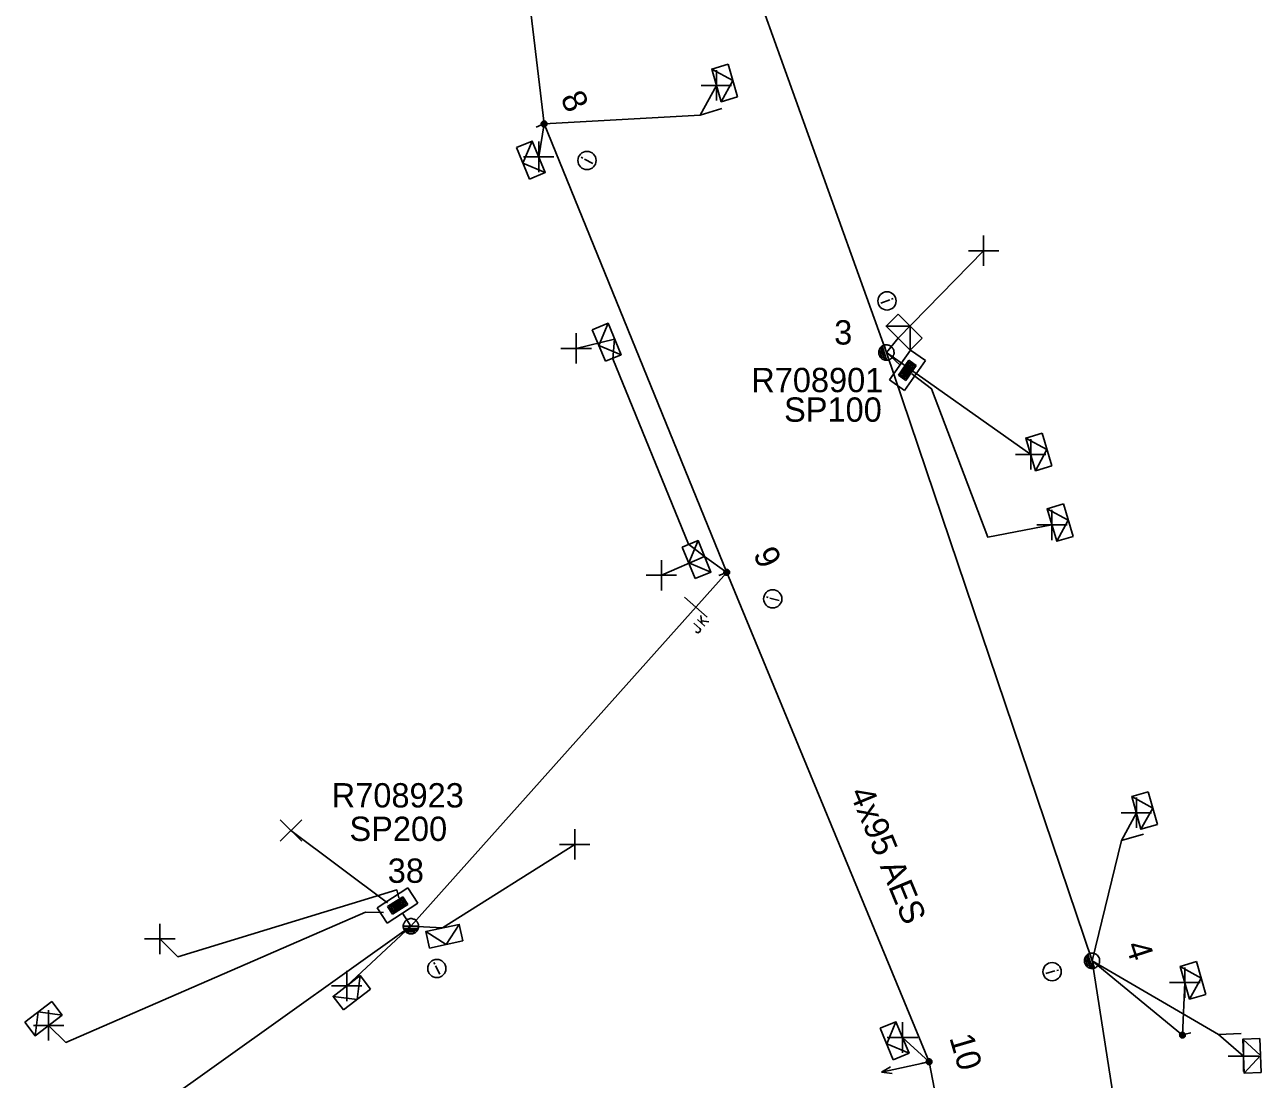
# Model space of a CAD drawing. Extents: x -540466 to -537383, y -1184038 to -1179972.
# Drawn here: x -537738 to -537687.2, y -1180420.7 to -1180377.4 of the extents above; entities that cross this region are included whole.
import ezdxf

# ---------------------------------------------------------------- set-up
doc = ezdxf.new("R2010")
doc.units = 0
for name, color, linetype in [('Vrstva 1', 7, 'Continuous'), ('Vrstva 10', 7, 'Continuous'), ('Vrstva 13', 7, 'Continuous'), ('Vrstva 14', 7, 'Continuous'), ('Vrstva 15', 7, 'Continuous'), ('Vrstva 18', 7, 'Continuous'), ('Vrstva 2', 7, 'Continuous'), ('Vrstva 28', 7, 'Continuous'), ('Vrstva 29', 7, 'Continuous'), ('Vrstva 30', 7, 'Continuous'), ('Vrstva 31', 7, 'Continuous'), ('Vrstva 34', 7, 'Continuous'), ('Vrstva 36', 7, 'Continuous'), ('Vrstva 5', 7, 'Continuous'), ('Vrstva 50', 7, 'Continuous'), ('Vrstva 51', 7, 'Continuous'), ('Vrstva 52', 7, 'Continuous'), ('Vrstva 54', 7, 'Continuous'), ('Vrstva 59', 7, 'Continuous'), ('Vrstva 8', 7, 'Continuous'), ('Vrstva 9', 7, 'Continuous')]:
    doc.layers.add(name, color=color, linetype=linetype)

# ---------------------------------------------------------------- blocks, each defined once
blk = doc.blocks.new('NN440')
at = {"layer": 'Vrstva 2'}
for points in [[(0.63, 0), (0.63, 0.06), (0.62, 0.13), (0.6, 0.19), (0.58, 0.25), (0.55, 0.31), (0.51, 0.37), (0.47, 0.42), (0.42, 0.46), (0.37, 0.51), (0.32, 0.54), (0.26, 0.57), (0.2, 0.59), (0.13, 0.61), (0.07, 0.62), (0, 0.63), (-0.06, 0.62), (-0.13, 0.61), (-0.19, 0.59), (-0.26, 0.57), (-0.31, 0.54), (-0.37, 0.51), (-0.42, 0.46), (-0.47, 0.42), (-0.51, 0.37), (-0.54, 0.31), (-0.57, 0.25), (-0.6, 0.19), (-0.62, 0.13), (-0.63, 0.06), (-0.63, 0), (-0.63, -0.07), (-0.62, -0.14), (-0.6, -0.2), (-0.57, -0.26), (-0.54, -0.32), (-0.51, -0.37), (-0.47, -0.43), (-0.42, -0.47), (-0.37, -0.51), (-0.31, -0.55), (-0.26, -0.58), (-0.19, -0.6), (-0.13, -0.62), (-0.06, -0.63), (0, -0.63), (0.07, -0.63), (0.13, -0.62), (0.2, -0.6), (0.26, -0.58), (0.32, -0.55), (0.37, -0.51), (0.42, -0.47), (0.47, -0.43), (0.51, -0.37), (0.55, -0.32), (0.58, -0.26), (0.6, -0.2), (0.62, -0.14), (0.63, -0.07), (0.63, 0)], [(-0.63, 0), (0.63, 0)], [(-0.6, -0.18), (0.57, -0.18)], [(-0.51, -0.32), (0.5, -0.32)], [(-0.37, -0.47), (0.35, -0.47)]]:
    blk.add_lwpolyline(points, dxfattribs=at)
blk = doc.blocks.new('NN560')
at = {"layer": 'Vrstva 2'}
for points in [[(1.999, -0.001), (1.59, 0.141)], [(0, -0.001), (1.999, -0.001)], [(1.999, -0.001), (1.59, -0.134)]]:
    blk.add_lwpolyline(points, dxfattribs=at)
blk = doc.blocks.new('NN840')
at = {"layer": 'Vrstva 15'}
for points in [[(0.003, 0.619), (0.003, -0.631)], [(-0.538, -0.385), (-0.538, -0.71)], [(-0.332, -0.385), (-0.332, -0.798)], [(-0.332, -0.641), (-0.125, -0.385)], [(-0.745, -0.71), (-0.745, -0.66)], [(-0.73, -0.764), (-0.745, -0.71)], [(-0.657, -0.798), (-0.73, -0.764)], [(-0.627, -0.798), (-0.657, -0.798)], [(-0.558, -0.764), (-0.627, -0.798)], [(-0.538, -0.71), (-0.558, -0.764)], [(-0.263, -0.557), (-0.091, -0.798)]]:
    blk.add_lwpolyline(points, dxfattribs=at)
blk = doc.blocks.new('NN770')
at = {"layer": 'Vrstva 10'}
for p, q in [((0.002, 0.187), (0.002, 0.263)), ((0.002, -0.276), (0.002, 0.111))]:
    blk.add_line(p, q, dxfattribs=at)
blk.add_circle((0, -0.008), 0.375, dxfattribs=at)
blk = doc.blocks.new('NN800')
at = {"layer": 'Vrstva 1'}
for points in [[(-0.442, 0.442), (0.442, -0.442)], [(-0.442, -0.442), (0.442, 0.442)]]:
    blk.add_lwpolyline(points, dxfattribs=at)
blk = doc.blocks.new('NN620')
at = {"layer": 'Vrstva 8'}
for points in [[(0.752, 0.004), (-0.748, 0.004)], [(-0.748, 0.004), (-0.748, -0.746)], [(0.752, -0.746), (0.752, 0.004)], [(0.368, -0.18), (-0.376, -0.18)], [(-0.376, -0.18), (-0.376, -0.558)], [(0.321, -0.227), (-0.329, -0.227)], [(-0.329, -0.227), (-0.329, -0.51)], [(0.274, -0.274), (-0.281, -0.274)], [(-0.281, -0.274), (-0.281, -0.463)], [(-0.281, -0.463), (0.274, -0.463)], [(0.227, -0.321), (-0.234, -0.321)], [(-0.234, -0.321), (-0.234, -0.416)], [(-0.234, -0.416), (0.227, -0.416)], [(-0.193, -0.369), (0.185, -0.369)], [(0.227, -0.416), (0.227, -0.321)], [(0.274, -0.463), (0.274, -0.274)], [(0.321, -0.51), (0.321, -0.227)], [(0.368, -0.558), (0.368, -0.18)], [(-0.748, -0.746), (0.752, -0.746)], [(-0.376, -0.558), (0.368, -0.558)], [(-0.329, -0.51), (0.321, -0.51)]]:
    blk.add_lwpolyline(points, dxfattribs=at)
blk = doc.blocks.new('NN630')
at = {"layer": 'Vrstva 9'}
for points in [[(-0.003, -0.7), (-0.703, 0)], [(-0.703, -0.7), (-0.703, 0), (0.697, 0), (0.697, -0.7)], [(-0.003, -0.7), (0.697, 0)], [(-0.703, -0.7), (0.697, -0.7)]]:
    blk.add_lwpolyline(points, dxfattribs=at)
blk = doc.blocks.new('NN500')
at = {"layer": 'Vrstva 2'}
for points in [[(0, -0.24), (0.02, -0.23), (0.05, -0.23), (0.07, -0.22), (0.09, -0.22), (0.12, -0.2), (0.14, -0.19), (0.16, -0.18), (0.17, -0.16), (0.19, -0.14), (0.2, -0.12), (0.21, -0.1), (0.22, -0.07), (0.23, -0.05), (0.23, -0.02), (0.23, 0), (0.23, 0.02), (0.23, 0.05), (0.22, 0.07), (0.21, 0.1), (0.2, 0.12), (0.19, 0.14), (0.17, 0.16), (0.16, 0.17), (0.14, 0.19), (0.12, 0.2), (0.09, 0.21), (0.07, 0.22), (0.05, 0.23), (0.02, 0.23), (0, 0.23), (-0.03, 0.23), (-0.05, 0.23), (-0.07, 0.22), (-0.1, 0.21), (-0.12, 0.2), (-0.14, 0.19), (-0.16, 0.17), (-0.18, 0.16), (-0.19, 0.14), (-0.2, 0.12), (-0.22, 0.1), (-0.22, 0.07), (-0.23, 0.05), (-0.23, 0.02), (-0.24, 0), (-0.23, -0.02), (-0.23, -0.05), (-0.22, -0.07), (-0.22, -0.1), (-0.2, -0.12), (-0.19, -0.14), (-0.18, -0.16), (-0.16, -0.18), (-0.14, -0.19), (-0.12, -0.2), (-0.1, -0.22), (-0.07, -0.22), (-0.05, -0.23), (-0.03, -0.23), (0, -0.24)], [(0, -0.24), (0.02, -0.23), (0.05, -0.23), (0.07, -0.22), (0.09, -0.22), (0.12, -0.2), (0.14, -0.19), (0.16, -0.18), (0.17, -0.16), (0.19, -0.14), (0.2, -0.12), (0.21, -0.1), (0.22, -0.07), (0.23, -0.05), (0.23, -0.02), (0.23, 0), (0.23, 0.02), (0.23, 0.05), (0.22, 0.07), (0.21, 0.1), (0.2, 0.12), (0.19, 0.14), (0.17, 0.16), (0.16, 0.17), (0.14, 0.19), (0.12, 0.2), (0.09, 0.21), (0.07, 0.22), (0.05, 0.23), (0.02, 0.23), (0, 0.23), (-0.03, 0.23), (-0.05, 0.23), (-0.07, 0.22), (-0.1, 0.21), (-0.12, 0.2), (-0.14, 0.19), (-0.16, 0.17), (-0.18, 0.16), (-0.19, 0.14), (-0.2, 0.12), (-0.22, 0.1), (-0.22, 0.07), (-0.23, 0.05), (-0.23, 0.02), (-0.24, 0), (-0.23, -0.02), (-0.23, -0.05), (-0.22, -0.07), (-0.22, -0.1), (-0.2, -0.12), (-0.19, -0.14), (-0.18, -0.16), (-0.16, -0.18), (-0.14, -0.19), (-0.12, -0.2), (-0.1, -0.22), (-0.07, -0.22), (-0.05, -0.23), (-0.03, -0.23), (0, -0.24)], [(0, -0.21), (0.02, -0.2), (0.04, -0.2), (0.06, -0.2), (0.08, -0.19), (0.1, -0.18), (0.12, -0.17), (0.14, -0.15), (0.15, -0.14), (0.16, -0.12), (0.18, -0.1), (0.19, -0.08), (0.19, -0.06), (0.2, -0.04), (0.2, -0.02), (0.2, 0), (0.2, 0.02), (0.2, 0.04), (0.19, 0.06), (0.19, 0.08), (0.18, 0.1), (0.16, 0.12), (0.15, 0.14), (0.14, 0.15), (0.12, 0.17), (0.1, 0.18), (0.08, 0.19), (0.06, 0.19), (0.04, 0.2), (0.02, 0.2), (0, 0.2), (-0.02, 0.2), (-0.04, 0.2), (-0.06, 0.19), (-0.08, 0.19), (-0.1, 0.18), (-0.12, 0.17), (-0.14, 0.15), (-0.15, 0.14), (-0.17, 0.12), (-0.18, 0.1), (-0.19, 0.08), (-0.2, 0.06), (-0.2, 0.04), (-0.21, 0.02), (-0.21, 0), (-0.21, -0.02), (-0.2, -0.04), (-0.2, -0.06), (-0.19, -0.08), (-0.18, -0.1), (-0.17, -0.12), (-0.15, -0.14), (-0.14, -0.15), (-0.12, -0.17), (-0.1, -0.18), (-0.08, -0.19), (-0.06, -0.2), (-0.04, -0.2), (-0.02, -0.2), (0, -0.21)], [(0, -0.18), (0.02, -0.18), (0.04, -0.17), (0.05, -0.17), (0.07, -0.16), (0.09, -0.15), (0.1, -0.14), (0.12, -0.13), (0.13, -0.12), (0.14, -0.1), (0.15, -0.09), (0.16, -0.07), (0.17, -0.05), (0.17, -0.04), (0.17, -0.02), (0.17, 0), (0.17, 0.02), (0.17, 0.04), (0.17, 0.05), (0.16, 0.07), (0.15, 0.09), (0.14, 0.1), (0.13, 0.12), (0.12, 0.13), (0.1, 0.14), (0.09, 0.15), (0.07, 0.16), (0.05, 0.17), (0.04, 0.17), (0.02, 0.17), (0, 0.18), (-0.02, 0.17), (-0.04, 0.17), (-0.06, 0.17), (-0.07, 0.16), (-0.09, 0.15), (-0.1, 0.14), (-0.12, 0.13), (-0.13, 0.12), (-0.14, 0.1), (-0.15, 0.09), (-0.16, 0.07), (-0.17, 0.05), (-0.17, 0.04), (-0.18, 0.02), (-0.18, 0), (-0.18, -0.02), (-0.17, -0.04), (-0.17, -0.05), (-0.16, -0.07), (-0.15, -0.09), (-0.14, -0.1), (-0.13, -0.12), (-0.12, -0.13), (-0.1, -0.14), (-0.09, -0.15), (-0.07, -0.16), (-0.06, -0.17), (-0.04, -0.17), (-0.02, -0.18), (0, -0.18)], [(0, -0.15), (0.01, -0.15), (0.03, -0.14), (0.04, -0.14), (0.06, -0.13), (0.07, -0.13), (0.08, -0.12), (0.1, -0.11), (0.11, -0.1), (0.12, -0.09), (0.13, -0.07), (0.13, -0.06), (0.14, -0.05), (0.14, -0.03), (0.14, -0.02), (0.14, 0), (0.14, 0.01), (0.14, 0.03), (0.14, 0.04), (0.13, 0.06), (0.13, 0.07), (0.12, 0.09), (0.11, 0.1), (0.1, 0.11), (0.08, 0.12), (0.07, 0.13), (0.06, 0.13), (0.04, 0.14), (0.03, 0.14), (0.01, 0.14), (0, 0.15), (-0.02, 0.14), (-0.03, 0.14), (-0.05, 0.14), (-0.06, 0.13), (-0.07, 0.13), (-0.09, 0.12), (-0.1, 0.11), (-0.11, 0.1), (-0.12, 0.09), (-0.13, 0.07), (-0.13, 0.06), (-0.14, 0.04), (-0.14, 0.03), (-0.15, 0.01), (-0.15, 0), (-0.15, -0.02), (-0.14, -0.03), (-0.14, -0.05), (-0.13, -0.06), (-0.13, -0.07), (-0.12, -0.09), (-0.11, -0.1), (-0.1, -0.11), (-0.09, -0.12), (-0.07, -0.13), (-0.06, -0.13), (-0.05, -0.14), (-0.03, -0.14), (-0.02, -0.15), (0, -0.15)], [(0, -0.12), (0.01, -0.12), (0.02, -0.11), (0.03, -0.11), (0.05, -0.11), (0.06, -0.1), (0.07, -0.09), (0.08, -0.09), (0.09, -0.08), (0.09, -0.07), (0.1, -0.06), (0.11, -0.05), (0.11, -0.04), (0.11, -0.02), (0.11, -0.01), (0.12, 0), (0.11, 0.01), (0.11, 0.02), (0.11, 0.04), (0.11, 0.05), (0.1, 0.06), (0.09, 0.07), (0.09, 0.08), (0.08, 0.09), (0.07, 0.09), (0.06, 0.1), (0.05, 0.11), (0.03, 0.11), (0.02, 0.11), (0.01, 0.12), (0, 0.12), (-0.01, 0.12), (-0.03, 0.11), (-0.04, 0.11), (-0.05, 0.11), (-0.06, 0.1), (-0.07, 0.09), (-0.08, 0.09), (-0.09, 0.08), (-0.1, 0.07), (-0.1, 0.06), (-0.11, 0.05), (-0.11, 0.04), (-0.12, 0.02), (-0.12, 0.01), (-0.12, 0), (-0.12, -0.01), (-0.12, -0.02), (-0.11, -0.04), (-0.11, -0.05), (-0.1, -0.06), (-0.1, -0.07), (-0.09, -0.08), (-0.08, -0.09), (-0.07, -0.09), (-0.06, -0.1), (-0.05, -0.11), (-0.04, -0.11), (-0.03, -0.11), (-0.01, -0.12), (0, -0.12)], [(0, -0.09), (0.01, -0.09), (0.02, -0.09), (0.03, -0.08), (0.03, -0.08), (0.04, -0.08), (0.05, -0.07), (0.06, -0.07), (0.06, -0.06), (0.07, -0.05), (0.07, -0.04), (0.08, -0.04), (0.08, -0.03), (0.08, -0.02), (0.09, -0.01), (0.09, 0), (0.09, 0.01), (0.08, 0.02), (0.08, 0.03), (0.08, 0.03), (0.07, 0.04), (0.07, 0.05), (0.06, 0.06), (0.06, 0.06), (0.05, 0.07), (0.04, 0.07), (0.03, 0.08), (0.03, 0.08), (0.02, 0.08), (0.01, 0.09), (0, 0.09), (-0.01, 0.09), (-0.02, 0.08), (-0.03, 0.08), (-0.04, 0.08), (-0.04, 0.07), (-0.05, 0.07), (-0.06, 0.06), (-0.07, 0.06), (-0.07, 0.05), (-0.08, 0.04), (-0.08, 0.03), (-0.08, 0.03), (-0.09, 0.02), (-0.09, 0.01), (-0.09, 0), (-0.09, -0.01), (-0.09, -0.02), (-0.08, -0.03), (-0.08, -0.04), (-0.08, -0.04), (-0.07, -0.05), (-0.07, -0.06), (-0.06, -0.07), (-0.05, -0.07), (-0.04, -0.08), (-0.04, -0.08), (-0.03, -0.08), (-0.02, -0.09), (-0.01, -0.09), (0, -0.09)], [(0, -0.06), (0, -0.06), (0.01, -0.06), (0.02, -0.05), (0.02, -0.05), (0.03, -0.05), (0.03, -0.05), (0.04, -0.04), (0.04, -0.04), (0.05, -0.03), (0.05, -0.03), (0.05, -0.02), (0.05, -0.02), (0.05, -0.01), (0.06, -0.01), (0.06, 0), (0.06, 0.01), (0.05, 0.01), (0.05, 0.02), (0.05, 0.02), (0.05, 0.03), (0.05, 0.03), (0.04, 0.04), (0.04, 0.04), (0.03, 0.05), (0.03, 0.05), (0.02, 0.05), (0.02, 0.05), (0.01, 0.06), (0, 0.06), (0, 0.06), (-0.01, 0.06), (-0.01, 0.06), (-0.02, 0.05), (-0.02, 0.05), (-0.03, 0.05), (-0.03, 0.05), (-0.04, 0.04), (-0.04, 0.04), (-0.05, 0.03), (-0.05, 0.03), (-0.05, 0.02), (-0.06, 0.02), (-0.06, 0.01), (-0.06, 0.01), (-0.06, 0), (-0.06, -0.01), (-0.06, -0.01), (-0.06, -0.02), (-0.05, -0.02), (-0.05, -0.03), (-0.05, -0.03), (-0.04, -0.04), (-0.04, -0.04), (-0.03, -0.05), (-0.03, -0.05), (-0.02, -0.05), (-0.02, -0.05), (-0.01, -0.06), (-0.01, -0.06), (0, -0.06)], [(0, -0.03), (0, -0.03), (0, -0.03), (0.01, -0.03), (0.01, -0.03), (0.01, -0.02), (0.02, -0.02), (0.02, -0.02), (0.02, -0.02), (0.02, -0.02), (0.02, -0.01), (0.02, -0.01), (0.03, -0.01), (0.03, -0.01), (0.03, 0), (0.03, 0), (0.03, 0), (0.03, 0.01), (0.03, 0.01), (0.02, 0.01), (0.02, 0.01), (0.02, 0.02), (0.02, 0.02), (0.02, 0.02), (0.02, 0.02), (0.01, 0.02), (0.01, 0.02), (0.01, 0.03), (0, 0.03), (0, 0.03), (0, 0.03), (0, 0.03), (-0.01, 0.03), (-0.01, 0.03), (-0.01, 0.02), (-0.02, 0.02), (-0.02, 0.02), (-0.02, 0.02), (-0.02, 0.02), (-0.02, 0.02), (-0.03, 0.01), (-0.03, 0.01), (-0.03, 0.01), (-0.03, 0.01), (-0.03, 0), (-0.03, 0), (-0.03, 0), (-0.03, -0.01), (-0.03, -0.01), (-0.03, -0.01), (-0.03, -0.01), (-0.02, -0.02), (-0.02, -0.02), (-0.02, -0.02), (-0.02, -0.02), (-0.02, -0.02), (-0.01, -0.03), (-0.01, -0.03), (-0.01, -0.03), (0, -0.03), (0, -0.03)], [(0.23, 0), (0.7, 0)]]:
    blk.add_lwpolyline(points, dxfattribs=at)
blk = doc.blocks.new('NN510')
at = {"layer": 'Vrstva 2'}
blk.add_lwpolyline([(0.001, 0.002), (0.001, 0.939)], dxfattribs=at)

msp = doc.modelspace()

# ---------------------------------------------------------------- linework, layer by layer
at = {"layer": 'Vrstva 5'}
msp.add_lwpolyline([(-537702.6, -1180390.87), (-537702.041, -1180391.386)], dxfattribs=at)
at = {"layer": 'Vrstva 50'}
for points in [[(-537716.607, -1180329.735), (-537712.25, -1180363.97), (-537702.6, -1180390.87)], [(-537719.309, -1180359.368), (-537716.668, -1180381.475), (-537709.164, -1180399.909)], [(-537702.6, -1180390.87), (-537694.15, -1180415.87), (-537689.5, -1180445.65)], [(-537709.164, -1180399.909), (-537722.14, -1180414.45)], [(-537709.164, -1180399.909), (-537700.846, -1180420.022), (-537698.223, -1180433.607), (-537690.098, -1180444.825)], [(-537722.14, -1180414.45), (-537737.733, -1180425.579)]]:
    msp.add_lwpolyline(points, dxfattribs=at)
at = {"layer": 'Vrstva 52'}
for points in [[(-537702.6, -1180390.87), (-537702.124, -1180390.278), (-537698.605, -1180386.687)], [(-537701.552, -1180391.753), (-537700.744, -1180392.36), (-537698.434, -1180398.46), (-537695.8, -1180397.957)], [(-537722.14, -1180414.45), (-537720.839, -1180414.519), (-537715.408, -1180411.087)], [(-537722.64, -1180413.287), (-537722.721, -1180412.957), (-537731.714, -1180415.706), (-537732.457, -1180414.973)], [(-537723.269, -1180413.891), (-537724.011, -1180413.873), (-537736.328, -1180419.226), (-537737.032, -1180418.53)], [(-537722.14, -1180414.45), (-537722.486, -1180413.91)]]:
    msp.add_lwpolyline(points, dxfattribs=at)
at = {"layer": 'Vrstva 54'}
for points in [[(-537716.668, -1180381.475), (-537710.259, -1180381.109), (-537709.586, -1180379.889)], [(-537716.668, -1180381.475), (-537716.888, -1180382.828)], [(-537702.6, -1180390.87), (-537696.673, -1180395.056)], [(-537709.164, -1180399.909), (-537710.076, -1180399.251)], [(-537694.15, -1180415.87), (-537692.941, -1180410.922), (-537692.33, -1180409.787)], [(-537722.14, -1180414.45), (-537724.781, -1180416.906)], [(-537700.846, -1180420.022), (-537701.941, -1180419.024)]]:
    msp.add_lwpolyline(points, dxfattribs=at)
at = {"layer": 'Vrstva 59'}
for points in [[(-537710.076, -1180399.251), (-537710.731, -1180398.746), (-537713.847, -1180391.133), (-537713.771, -1180390.32), (-537715.351, -1180390.701)], [(-537710.076, -1180399.251), (-537711.849, -1180400.025)], [(-537723.1, -1180413.484), (-537727.069, -1180410.514)]]:
    msp.add_lwpolyline(points, dxfattribs=at)
at = {"layer": 'Vrstva 8'}
for points in [[(-537694.15, -1180415.87), (-537688.956, -1180418.898), (-537687.928, -1180419.793)], [(-537694.15, -1180415.87), (-537690.433, -1180418.926), (-537690.336, -1180416.771)]]:
    msp.add_lwpolyline(points, dxfattribs=at)

# ---------------------------------------------------------------- block references
at = {"layer": 'Vrstva 13'}
for name, p, rotation in [('NN510', (-537710.26, -1180381.109), -73.7431555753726), ('NN510', (-537692.941, -1180410.922), -74.3436555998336), ('NN510', (-537688.956, -1180418.897), -87.42383336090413), ('NN560', (-537700.846, -1180420.022), -167.49625553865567)]:
    msp.add_blockref(name, p, dxfattribs=dict(at, rotation=rotation))
for name, p, xscale, yscale, rotation in [('NN500', (-537716.668, -1180381.475), 0.5000000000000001, 0.5, -157.40799998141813), ('NN440', (-537702.6, -1180390.87), 0.49999999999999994, 0.5000000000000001, -72.17175835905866), ('NN500', (-537709.164, -1180399.909), 0.5, 0.5000000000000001, -157.66299992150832), ('NN440', (-537694.15, -1180415.87), 0.49999999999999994, 0.5000000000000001, -72.22963338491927), ('NN500', (-537690.433, -1180418.926), 0.5, 0.49999999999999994, 16.065999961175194), ('NN500', (-537700.846, -1180420.022), 0.49999999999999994, 0.5, -168.47899986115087)]:
    msp.add_blockref(name, p, dxfattribs=dict(at, xscale=xscale, yscale=yscale, rotation=rotation))
at = {"layer": 'Vrstva 13', "xscale": 0.5, "yscale": 0.5}
msp.add_blockref('NN440', (-537722.14, -1180414.45), dxfattribs=at)
at = {"layer": 'Vrstva 18', "rotation": 48.2551305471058}
msp.add_blockref('NN840', (-537710.437, -1180401.336), dxfattribs=at)
at = {"layer": 'Vrstva 28'}
for p, rotation in [((-537702.041, -1180391.386), 54.81828330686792), ((-537722.486, -1180413.91), -147.05078617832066)]:
    msp.add_blockref('NN620', p, dxfattribs=dict(at, rotation=rotation))
at = {"layer": 'Vrstva 31'}
for p, rotation in [((-537709.586, -1180379.889), 106.25684442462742), ((-537716.888, -1180382.828), -67.40791660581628), ((-537702.124, -1180390.278), 135), ((-537713.771, -1180390.32), -67.4120944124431), ((-537696.673, -1180395.056), 106.76492772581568), ((-537695.8, -1180397.957), 106.67501671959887), ((-537710.076, -1180399.251), -67.65359163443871), ((-537692.33, -1180409.787), 105.65634440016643), ((-537720.839, -1180414.519), 12.028730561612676), ((-537690.336, -1180416.771), 106.06994721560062), ((-537724.781, -1180416.906), 37.6665139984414), ((-537737.032, -1180418.53), -142.71050009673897), ((-537701.941, -1180419.024), -67.35554174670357), ((-537687.928, -1180419.793), 92.57616670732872)]:
    msp.add_blockref('NN630', p, dxfattribs=dict(at, rotation=rotation))
at = {"layer": 'Vrstva 34'}
for p, rotation in [((-537709.586, -1180379.889), 45), ((-537716.888, -1180382.828), 45), ((-537698.605, -1180386.687), 45), ((-537715.351, -1180390.701), 45), ((-537696.673, -1180395.056), 44.99999995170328), ((-537695.8, -1180397.957), 45), ((-537711.849, -1180400.024), 45), ((-537692.33, -1180409.787), 44.99999995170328), ((-537715.408, -1180411.087), 45), ((-537732.457, -1180414.973), 45), ((-537724.781, -1180416.906), 45), ((-537690.336, -1180416.771), 45.00000009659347), ((-537737.032, -1180418.53), 45), ((-537701.941, -1180419.024), 45), ((-537687.928, -1180419.793), 44.99999995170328)]:
    msp.add_blockref('NN800', p, dxfattribs=dict(at, rotation=rotation))
msp.add_blockref('NN800', (-537727.069, -1180410.514), dxfattribs=at)
at = {"layer": 'Vrstva 36'}
for p, rotation in [((-537714.912, -1180382.973), 61.38954162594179), ((-537702.567, -1180388.747), -69.34108885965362), ((-537707.279, -1180400.994), 73.73979446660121), ((-537721.078, -1180416.183), 27.349874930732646), ((-537695.784, -1180416.318), -74.89890277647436)]:
    msp.add_blockref('NN770', p, dxfattribs=dict(at, rotation=rotation))

# ---------------------------------------------------------------- texts
at = {"layer": 'Vrstva 14'}
for s, rotation, p in [('8', 295.816, (-537716.018, -1180380.414)), ('3', 359.956, (-537704.748, -1180390.543)), ('9', 294.97, (-537708.095, -1180399.15)), ('4', 287.77, (-537692.779, -1180415.235)), ('10', 286.394, (-537700.023, -1180419.033))]:
    msp.add_text(s, height=1, rotation=rotation, dxfattribs=at).set_placement(p)
msp.add_text('38', height=1, dxfattribs=at).set_placement((-537723.093, -1180412.668))
at = {"layer": 'Vrstva 29'}
for s, p in [('R708901', (-537708.156, -1180392.501)), ('R708923', (-537725.395, -1180409.571))]:
    msp.add_text(s, height=1, dxfattribs=at).set_placement(p)
at = {"layer": 'Vrstva 30'}
for s, p in [('SP100', (-537706.806, -1180393.716)), ('SP200', (-537724.666, -1180410.947))]:
    msp.add_text(s, height=1, dxfattribs=at).set_placement(p)
at = {"layer": 'Vrstva 51'}
msp.add_text('4x95 AES', height=1, rotation=292.468, dxfattribs=at).set_placement((-537704.13, -1180408.963))

doc.saveas('drawing.dxf')
